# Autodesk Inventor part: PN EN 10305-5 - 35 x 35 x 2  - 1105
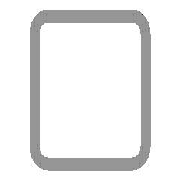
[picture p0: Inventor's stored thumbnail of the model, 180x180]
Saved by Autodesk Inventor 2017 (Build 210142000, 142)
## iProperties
Created: 2016-02
Part Number: PN EN 10305-5 - 35 x 35 x 2  - 1105
Material: Stal, miękka
Description: Rury stalowe do zastosowań precyzyjnych -  (Część 5: Rury kwadratowe, spawane, wymiarowane na zimno)
Document SubType Name: Modeling
Standard: PN
Designer: X
Standards Organization: PN
Language: pl-PL
Size Designation: 35 x 35 x 2
Categories: <MemberInstance><Categories><Category DisplayName="Kształtowniki konstrukcyjne" InternalName="089c4875-fa83-4c05-b084-43b9cc11f5ed" Mnemonic="GRDR"><CategoryPar
Stock Number: 35 x 35 x 2
Density: 7.85 g/cm^3
Appearance: Częściowo polerowana
_CCFamilyMember: 22
_CCFamilyDisplayName: PN EN 10305-5 (Rury kwadratowe, spawane, wymiarowane na zimno) - Rury stalowe do zastosowań precyzyjnych -  (Część 5: Rury kwadratowe, spawane, wymiarowane na z
_FrameMemberDoc: Frame Member File
_Version: 15.0.0
_GetPNFromCC: 1
G_L: 1105,000 mm
G_W: 35,000 mm
G_H: 35,000 mm
IsCustomPart: 1
Author: X
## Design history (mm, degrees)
node "Płaszczyzna początkowa"
node "Płaszczyzna końcowa"
sketch "Szkic"
  geometry: L1 (-17.5, -14.5)-(-17.5, 14.5); L2 (-14.5, 17.5)-(14.5, 17.5); L3 (17.5, 14.5)-(17.5, -14.5); L4 (14.5, -17.5)-(-14.5, -17.5); L5 (-14.5, 15.5)-(14.5, 15.5); L6 (15.5, 14.5)-(15.5, -14.5); L7 (14.5, -15.5)-(-14.5, -15.5); L8 (-15.5, -14.5)-(-15.5, 14.5); L9 (0, 25.37)-(0, -25.37) reference; L10 (-25.37, 0)-(25.37, 0) reference; A1 r 3 centre (-14.5, -14.5) between (-17.5, -14.5) and (-14.5, -17.5); A2 r 3 centre (-14.5, 14.5) between (-14.5, 17.5) and (-17.5, 14.5); A3 r 3 centre (14.5, 14.5) between (17.5, 14.5) and (14.5, 17.5); A4 r 3 centre (14.5, -14.5) between (14.5, -17.5) and (17.5, -14.5); A5 r 1 centre (-14.5, 14.5) between (-14.5, 15.5) and (-15.5, 14.5); A6 r 1 centre (14.5, 14.5) between (15.5, 14.5) and (14.5, 15.5); A7 r 1 centre (14.5, -14.5) between (14.5, -15.5) and (15.5, -14.5); A8 r 1 centre (-14.5, -14.5) between (-15.5, -14.5) and (-14.5, -15.5)
  constraints: 16 end point, 16 point on circle, 8 centre point, 8 tangent, 4 parallel, 3 equal radius, 2 perpendicular, 7 other
  dimensions: "d7" = 3 radius of A1 (= G_IR); "d10" = 35 distance between parallel lines of L2 L4 (= G_H); "d11" = 35 distance between parallel lines of L1 L3 (= G_W); "d12" = 2 distance between parallel lines of L3 L6 (= G_T); "d15" = 17.5 distance between parallel lines of L2 L10 (= 0.5 x d10); "d16" = 17.5 distance between parallel lines of L9 L3 (= 0.5 x d11)
extrude "Bryła" new body sketch "Szkic" stored distance "d3" = 1105 (= G_L); taper "d4" = 0 deg
node "Driven Length"
  sketch "Sketch3"
    geometry: L1 (0, 0)-(10, 0) reference
    constraints: 2 end point, 1 horizontal
  workplane "Work Plane3"
  sketch "Sketch4"
    geometry: L1 (-2, 0)-(12, 0) reference; L2 (-2, 1105)-(12, 1105) reference
    dimensions: "d18" = 1105 distance between parallel lines of L1 L2 (derived)
body "Solid1"
other parameters: "G_W" = 35 [user parameter; used in 1 equation term], "G_H" = 35 [user parameter; used in 1 equation term], "G_T" = 2 [user parameter; used in 1 equation term], "G_IR" = 3 [user parameter; used in 1 equation term], "G_L" = 1105 (= d18) [user parameter; used in 1 equation term], "G_OFFSET_START" = 0 [user parameter; used in 1 equation term], "G_OFFSET_END" = -35 [user parameter; used in 1 equation term], "d13" = 0 (computed from G_OFFSET_START), "d14" = 1105 (= G_OFFSET_END + B_L), "d17" = 90 deg
